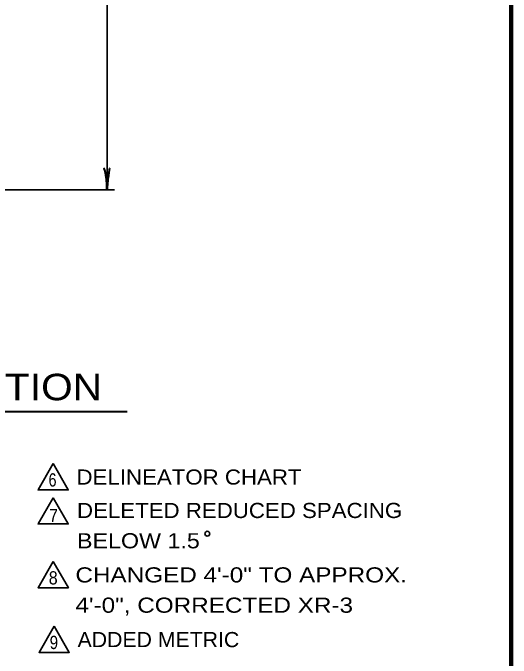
# Model space of a CAD drawing. Extents: x -89 to 766, y -60 to 484.
# Drawn here: x 680.8 to 759.8, y 69.2 to 171.5 of the extents above; entities that cross this region are included whole.
import ezdxf

# ---------------------------------------------------------------- set-up
doc = ezdxf.new("R2010")
doc.units = 0
doc.header["$LTSCALE"] = 1.1
doc.layers.add('1', color=7, linetype='Continuous', lineweight=35)

msp = doc.modelspace()

# ---------------------------------------------------------------- linework, layer by layer
at = {"layer": '1', "lineweight": 158}
msp.add_line((759.817, -48.017), (759.817, 478.083), dxfattribs=at)
at = {"layer": '1', "lineweight": 13}
msp.add_line((759.817, -48.017), (759.817, 478.083), dxfattribs=at)
at = {"layer": '1'}
for p, q in [((695.712, 271.817), (695.712, 143.417)), ((674.112, 143.417), (696.912, 143.417))]:
    msp.add_line(p, q, dxfattribs=at)
at = {"layer": '1', "lineweight": 40}
msp.add_line((602.417, 108.258), (698.915, 108.258), dxfattribs=at)
at = {"layer": '1'}
for points in [[(687.16, 100.017), (684.76, 95.86), (689.56, 95.86)], [(687.16, 94.619), (684.76, 90.462), (689.56, 90.462)], [(687.185, 84.494), (684.785, 80.337), (689.585, 80.337)], [(687.329, 74.251), (684.929, 70.094), (689.729, 70.094)]]:
    msp.add_lwpolyline(points, close=True, dxfattribs=at)
msp.add_circle((711.618, 88.907), 0.382, dxfattribs=at)
at = {"layer": '1', "lineweight": 40}
for centre, major_axis, ratio, start_param, end_param in [((695.381, 144.726), (0.187, -2.143), 0.122415, 0.8963533, 3.1415927), ((695.966, 144.762), (-0.211, -2.108), 0.07063, 3.1407148, 5.41811)]:
    msp.add_ellipse(centre, major_axis=major_axis, ratio=ratio, start_param=start_param, end_param=end_param, dxfattribs=at)

# ---------------------------------------------------------------- texts
at = {"layer": '1'}
for s, height, width, p in [('TYPICAL XR-3 INSTALLATION', 4.2, 1.15, (603.769, 110.062)), ('6', 2.1, 0.8, (686.444, 96.385)), ('DELINEATOR CHART', 2.4, 1.1, (690.869, 96.69)), ('DELETED REDUCED SPACING', 2.4, 1.1, (690.945, 91.39)), ('7', 2.1, 0.9, (686.52, 90.738)), ('BELOW 1.5', 2.4, 1.15, (690.945, 86.59)), ('8', 2.1, 0.9, (686.469, 80.862)), ('CHANGED 4\'-0" TO APPROX.', 2.4, 1.2, (690.694, 81.178)), ('4\'-0", CORRECTED XR-3', 2.4, 1.2, (690.694, 76.378)), ('9', 2.1, 0.85, (686.614, 70.618)), ('ADDED METRIC', 2.4, 1.05, (691.038, 70.923))]:
    msp.add_text(s, height=height, dxfattribs=dict(at, width=width)).set_placement(p)

doc.saveas('drawing.dxf')
